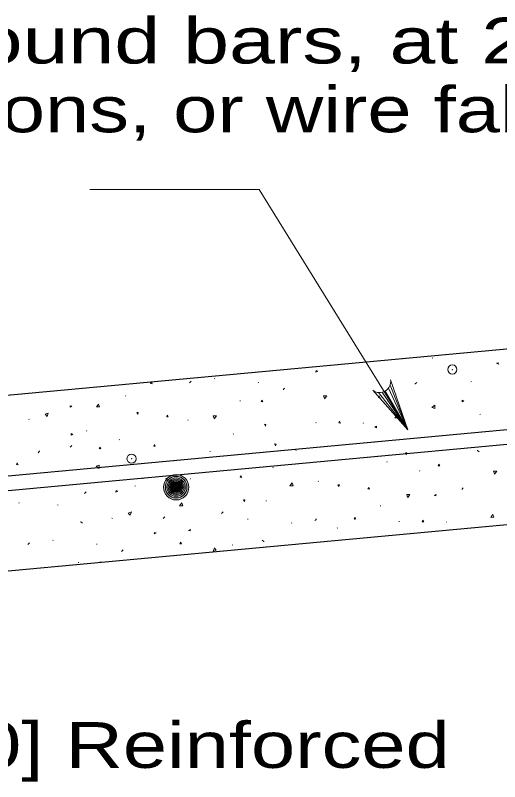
# Model space of a CAD drawing. Extents: x 1083.1 to 1117.1, y 697.4 to 741.4.
# Drawn here: x 1105.172 to 1106.825, y 723.186 to 725.801 of the extents above; entities that cross this region are included whole.
import ezdxf

# ---------------------------------------------------------------- set-up
doc = ezdxf.new("R2010")
doc.units = 0
doc.header["$LTSCALE"] = 0.062
doc.header["$PDMODE"] = 32
doc.header["$PDSIZE"] = 0.031
doc.layers.add('1', color=7, linetype='Continuous', lineweight=13)

msp = doc.modelspace()

# ---------------------------------------------------------------- hatches: boundary and pattern name
at = {"layer": '1'}
h = msp.add_hatch(color=256, dxfattribs=at)
edge = h.paths.add_edge_path()
edge.add_ellipse((1105.72135, 724.19072), major_axis=(0.04324, 0), ratio=0.9998948, start_angle=0, end_angle=360)
h = msp.add_hatch(color=256, dxfattribs=at)
edge = h.paths.add_edge_path()
edge.add_ellipse((1105.72121, 724.19093), major_axis=(0.03676, 0), ratio=0.9998948, start_angle=0, end_angle=360)
h = msp.add_hatch(color=256, dxfattribs=at)
edge = h.paths.add_edge_path()
edge.add_ellipse((1105.7211, 724.19111), major_axis=(0.03124, 0), ratio=0.9998948, start_angle=0, end_angle=360)
h = msp.add_hatch(color=256, dxfattribs=at)
edge = h.paths.add_edge_path()
edge.add_ellipse((1105.721, 724.19126), major_axis=(0.02656, 0), ratio=0.9998948, start_angle=0, end_angle=360)
h = msp.add_hatch(color=256, dxfattribs=at)
edge = h.paths.add_edge_path()
edge.add_ellipse((1105.72092, 724.19139), major_axis=(0.02257, 0), ratio=0.9998948, start_angle=0, end_angle=360)
h = msp.add_hatch(color=256, dxfattribs=at)
edge = h.paths.add_edge_path()
edge.add_ellipse((1105.72085, 724.1915), major_axis=(0.01919, 0), ratio=0.9998948, start_angle=0, end_angle=360)
h = msp.add_hatch(color=256, dxfattribs=at)
edge = h.paths.add_edge_path()
edge.add_ellipse((1105.72079, 724.19159), major_axis=(0.01631, 0), ratio=0.9998948, start_angle=0, end_angle=360)
h = msp.add_hatch(color=256, dxfattribs=at)
edge = h.paths.add_edge_path()
edge.add_ellipse((1105.72074, 724.19167), major_axis=(0.01386, 0), ratio=0.9998948, start_angle=0, end_angle=360)
h = msp.add_hatch(color=256, dxfattribs=at)
edge = h.paths.add_edge_path()
edge.add_ellipse((1105.72069, 724.19173), major_axis=(0.01178, 0), ratio=0.9998948, start_angle=0, end_angle=360)
h = msp.add_hatch(color=256, dxfattribs=at)
edge = h.paths.add_edge_path()
edge.add_ellipse((1105.72066, 724.19179), major_axis=(0.01002, 0), ratio=0.9998948, start_angle=0, end_angle=360)
h = msp.add_hatch(color=256, dxfattribs=at)
edge = h.paths.add_edge_path()
edge.add_ellipse((1105.72062, 724.19184), major_axis=(0.00851, 0), ratio=0.9998948, start_angle=0, end_angle=360)
h = msp.add_hatch(color=256, dxfattribs=at)
edge = h.paths.add_edge_path()
edge.add_ellipse((1105.7206, 724.19188), major_axis=(0.00724, 0), ratio=0.9998948, start_angle=0, end_angle=360)
h = msp.add_hatch(color=256, dxfattribs=at)
edge = h.paths.add_edge_path()
edge.add_ellipse((1105.72058, 724.19192), major_axis=(0.00615, 0), ratio=0.9998948, start_angle=0, end_angle=360)
h = msp.add_hatch(color=256, dxfattribs=at)
edge = h.paths.add_edge_path()
edge.add_ellipse((1105.72056, 724.19195), major_axis=(0.00523, 0), ratio=0.9998948, start_angle=0, end_angle=360)
h = msp.add_hatch(color=256, dxfattribs=at)
edge = h.paths.add_edge_path()
edge.add_ellipse((1105.72054, 724.19197), major_axis=(0.00444, 0), ratio=0.9998948, start_angle=0, end_angle=360)
h = msp.add_hatch(color=256, dxfattribs=at)
edge = h.paths.add_edge_path()
edge.add_ellipse((1105.72053, 724.19199), major_axis=(0.00378, 0), ratio=0.9998948, start_angle=0, end_angle=360)
h = msp.add_hatch(color=256, dxfattribs=at)
edge = h.paths.add_edge_path()
edge.add_ellipse((1105.72051, 724.19201), major_axis=(0.00321, 0), ratio=0.9998948, start_angle=0, end_angle=360)

# ---------------------------------------------------------------- linework, layer by layer
for p, q in [((1105.42633, 725.20642), (1106.00458, 725.20642)), ((1106.51225, 724.38708), (1106.00458, 725.20642)), ((1106.595, 724.631), (1106.597, 724.63175)), ((1105.85167, 724.56108), (1105.85317, 724.56233)), ((1106.00233, 724.54925), (1106.0015, 724.54725)), ((1106.72717, 724.55025), (1106.72908, 724.551)), ((1106.44558, 724.52883), (1106.51225, 724.38708)), ((1106.45142, 724.53942), (1106.51225, 724.38708)), ((1105.54933, 724.50333), (1105.54867, 724.50133)), ((1106.41167, 724.51383), (1106.51225, 724.38708)), ((1106.424, 724.51475), (1106.51225, 724.38708)), ((1106.43458, 724.51908), (1106.51225, 724.38708)), ((1105.93992, 724.48683), (1105.93925, 724.48483)), ((1105.21808, 724.4225), (1105.22008, 724.42175)), ((1105.76192, 724.42025), (1105.76117, 724.41825)), ((1106.75775, 724.439), (1106.75967, 724.43967)), ((1106.19892, 724.41208), (1106.19825, 724.41008)), ((1106.36025, 724.41025), (1106.35958, 724.40825)), ((1105.41542, 724.38258), (1105.41617, 724.38458)), ((1105.91633, 724.37333), (1105.91567, 724.37142)), ((1105.52675, 724.352), (1105.52742, 724.35392)), ((1106.39892, 724.34192), (1106.39883, 724.34192)), ((1105.83667, 724.31242), (1105.83817, 724.31367)), ((1106.13117, 724.31783), (1106.12958, 724.31667)), ((1106.44108, 724.27825), (1106.44033, 724.27625)), ((1106.05142, 724.25692), (1106.05208, 724.25892)), ((1106.55233, 724.24758), (1106.55167, 724.24567)), ((1105.6075, 724.21992), (1105.60817, 724.22192)), ((1105.76883, 724.21817), (1105.76967, 724.22017)), ((1106.20583, 724.20992), (1106.20658, 724.21192)), ((1105.58233, 724.19525), (1105.58075, 724.194)), ((1105.18492, 724.13883), (1105.18408, 724.13683)), ((1105.31883, 724.13008), (1105.31683, 724.13075)), ((1106.02783, 724.14333), (1106.02858, 724.14533)), ((1106.41842, 724.12683), (1106.41908, 724.12883)), ((1105.50208, 724.0855), (1105.50392, 724.08467)), ((1105.9655, 724.08108), (1105.96625, 724.08308)), ((1106.11608, 724.06908), (1106.11467, 724.068)), ((1106.27225, 724.05192), (1106.27075, 724.05083)), ((1106.48275, 724.075), (1106.48208, 724.07308)), ((1106.64425, 724.07325), (1106.64342, 724.07125)), ((1105.30017, 724.0095), (1105.30167, 724.01075)), ((1105.45075, 723.99758), (1105.45, 723.99567)), ((1105.91425, 723.99325), (1105.91225, 723.99392)), ((1105.38842, 723.93525), (1105.38767, 723.93333)), ((1105.46217, 723.93675), (1105.461, 723.93333)), ((1105.46383, 723.93367), (1105.46217, 723.93675))]:
    msp.add_line(p, q, dxfattribs=at)
at = {"layer": '1', "lineweight": 25}
for p, q in [((1110.5145, 724.72675), (1103.31092, 724.05875)), ((1110.51908, 724.67717), (1103.29317, 724.007)), ((1110.14883, 724.368), (1103.29017, 723.73208))]:
    msp.add_line(p, q, dxfattribs=at)
msp.add_lwpolyline([(1110.14883, 724.96767), (1107.49917, 724.722), (1103.29017, 724.33175)], dxfattribs=at)
at = {"layer": '1'}
for points in [[(1106.81483, 724.61367), (1106.82033, 724.61567), (1106.82117, 724.61033)], [(1106.20442, 724.58658), (1106.19883, 724.58858), (1106.198, 724.58325)], [(1106.41425, 724.50267), (1106.41225, 724.497), (1106.41758, 724.49625)], [(1106.01375, 724.48833), (1106.01183, 724.48275), (1106.01708, 724.48192)], [(1106.70317, 724.48442), (1106.69758, 724.48258), (1106.69692, 724.48775)], [(1105.36542, 724.46717), (1105.35983, 724.46908), (1105.35908, 724.46383)], [(1105.59008, 724.43967), (1105.59208, 724.44525), (1105.58683, 724.446)], [(1105.69108, 724.437), (1105.68908, 724.43142), (1105.69433, 724.43067)], [(1106.02558, 724.39933), (1106.02758, 724.40492), (1106.02242, 724.40558)], [(1106.27892, 724.41575), (1106.27692, 724.41025), (1106.28217, 724.4095)], [(1106.39892, 724.39592), (1106.4045, 724.39392), (1106.40517, 724.39917)], [(1105.369, 724.372), (1105.36342, 724.374), (1105.36258, 724.36875)], [(1105.461, 724.328), (1105.459, 724.32242), (1105.46425, 724.32175)], [(1105.64675, 724.33692), (1105.64492, 724.33133), (1105.65008, 724.3305)], [(1106.06, 724.33233), (1106.062, 724.33783), (1106.05667, 724.33867)], [(1106.50675, 724.30217), (1106.50875, 724.30775), (1106.50358, 724.30842)], [(1105.17833, 724.27375), (1105.17642, 724.26817), (1105.18158, 724.2675)], [(1106.61775, 724.26983), (1106.61583, 724.26425), (1106.62117, 724.2635)], [(1105.68883, 724.21442), (1105.69083, 724.22), (1105.68558, 724.22067)], [(1105.94217, 724.23092), (1105.94017, 724.22533), (1105.94542, 724.22458)], [(1106.27675, 724.19325), (1106.27867, 724.19883), (1106.2735, 724.19958)], [(1106.37767, 724.1905), (1106.37567, 724.185), (1106.38092, 724.18425)], [(1105.52175, 724.17792), (1105.51617, 724.17992), (1105.51542, 724.17458)], [(1106.60233, 724.16317), (1106.60792, 724.16117), (1106.60867, 724.16642)], [(1105.954, 724.14192), (1105.95592, 724.14742), (1105.95075, 724.14825)], [(1106.33167, 724.08025), (1106.33367, 724.08592), (1106.3285, 724.08658)], [(1106.56275, 724.07875), (1106.56083, 724.07325), (1106.56617, 724.0725)], [(1105.65292, 724.035), (1105.64725, 724.037), (1105.6465, 724.03175)], [(1105.76333, 724.04367), (1105.76892, 724.04167), (1105.76975, 724.04692)], [(1105.73742, 724.00367), (1105.73933, 723.998), (1105.73417, 723.99733)]]:
    msp.add_lwpolyline(points, close=True, dxfattribs=at)
for points in [[(1105.63575, 724.54925), (1105.63408, 724.54442), (1105.63942, 724.54358), (1105.6365, 724.54933)], [(1105.77275, 724.55258), (1105.77133, 724.552), (1105.76708, 724.547)], [(1106.453, 724.55758), (1106.51225, 724.38708), (1106.392, 724.52167)], [(1106.09167, 724.5285), (1106.09033, 724.52792), (1106.08617, 724.52292)], [(1106.5365, 724.54233), (1106.53708, 724.54375), (1106.54208, 724.54792)], [(1105.23158, 724.51175), (1105.23158, 724.51167), (1105.23192, 724.51175)], [(1106.2275, 724.49283), (1106.23492, 724.50267), (1106.224, 724.5025), (1106.22742, 724.49308)], [(1105.45633, 724.47433), (1105.449, 724.46458), (1105.45983, 724.46475), (1105.4565, 724.47417)], [(1106.59417, 724.46283), (1106.604, 724.47025), (1106.60383, 724.45925), (1106.59433, 724.46275)], [(1105.28075, 724.432), (1105.28433, 724.44375), (1105.27417, 724.43983), (1105.28067, 724.43217)], [(1105.85092, 724.42467), (1105.85842, 724.4345), (1105.84742, 724.43442), (1105.85075, 724.42492)], [(1106.47542, 724.43717), (1106.46792, 724.42742), (1106.47892, 724.42758), (1106.47542, 724.437)], [(1106.49775, 724.42108), (1106.49633, 724.4205), (1106.49217, 724.4155)], [(1105.25625, 724.31392), (1105.25483, 724.31333), (1105.25067, 724.30842)], [(1105.35975, 724.328), (1105.36108, 724.32867), (1105.36533, 724.33367)], [(1106.74933, 724.31717), (1106.75, 724.31575), (1106.755, 724.31158)], [(1105.44858, 724.2625), (1105.45833, 724.25508), (1105.45817, 724.266), (1105.44875, 724.26258)], [(1106.80775, 724.23575), (1106.81525, 724.24558), (1106.80425, 724.24542), (1106.80767, 724.236)], [(1106.11683, 724.2055), (1106.1095, 724.19575), (1106.12033, 724.19592), (1106.117, 724.20533)], [(1106.70117, 724.18833), (1106.69975, 724.18775), (1106.69558, 724.18275)], [(1105.41375, 724.17525), (1105.41242, 724.17458), (1105.40817, 724.16967)], [(1106.51133, 724.15583), (1106.51883, 724.16567), (1106.50792, 724.1655), (1106.51125, 724.156)], [(1105.74025, 724.13733), (1105.73283, 724.12758), (1105.74383, 724.12775), (1105.74033, 724.13717)], [(1105.56475, 724.095), (1105.56833, 724.10675), (1105.558, 724.10283), (1105.5645, 724.09517)], [(1105.87608, 724.10167), (1105.8775, 724.10225), (1105.88167, 724.10725)], [(1105.68233, 724.08933), (1105.681, 724.08892), (1105.67675, 724.08392)], [(1106.195, 724.07758), (1106.19642, 724.07817), (1106.20058, 724.08317)], [(1106.80217, 724.09783), (1106.79475, 724.08808), (1106.80575, 724.08825), (1106.80225, 724.09767)], [(1105.39567, 724.07425), (1105.39633, 724.07292), (1105.40133, 724.06867)], [(1105.22117, 724.00117), (1105.21975, 724.0005), (1105.21558, 723.9955)], [(1106.0205, 724.00442), (1106.01992, 724.00583), (1106.01492, 724.01)], [(1105.54017, 723.97692), (1105.53883, 723.97633), (1105.53467, 723.97142)], [(1105.85158, 723.98375), (1105.848, 723.97192), (1105.85817, 723.97583), (1105.85167, 723.9835)]]:
    msp.add_lwpolyline(points, dxfattribs=at)
msp.add_arc((1106.4152, 724.55193), 0.0382, 232.54301, 8.36914, dxfattribs=at)
for centre, major_axis in [((1105.72135, 724.19072), (0.04324, 0)), ((1105.72121, 724.19093), (0.03676, 0)), ((1105.7211, 724.19111), (0.03124, 0)), ((1105.721, 724.19126), (0.02656, 0)), ((1105.72092, 724.19139), (0.02257, 0)), ((1105.72085, 724.1915), (0.01919, 0)), ((1105.72079, 724.19159), (0.01631, 0)), ((1105.72074, 724.19167), (0.01386, 0)), ((1105.72069, 724.19173), (0.01178, 0)), ((1105.72066, 724.19179), (0.01002, 0)), ((1105.72062, 724.19184), (0.00851, 0)), ((1105.7206, 724.19188), (0.00724, 0)), ((1105.72058, 724.19192), (0.00615, 0)), ((1105.72056, 724.19195), (0.00523, 0)), ((1105.72054, 724.19197), (0.00444, 0)), ((1105.72053, 724.19199), (0.00378, 0)), ((1105.72051, 724.19201), (0.00321, 0))]:
    msp.add_ellipse(centre, major_axis=major_axis, ratio=0.999895, dxfattribs=at)
for p in [(1106.66342, 724.59242), (1105.56892, 724.28825)]:
    msp.add_point(p, dxfattribs=at)

# ---------------------------------------------------------------- texts
for s, width, p in [('#3 [#10M] round bars, at 24" [600] o.c.', 1.35, (1103.61583, 725.63633)), ('in two directions, or wire fabric according ', 1.3, (1103.61583, 725.40167)), ('6" [150] Reinforced', 1.3, (1104.3425, 723.2335))]:
    msp.add_text(s, height=0.156, dxfattribs=dict(at, width=width)).set_placement(p)

doc.saveas('drawing.dxf')
